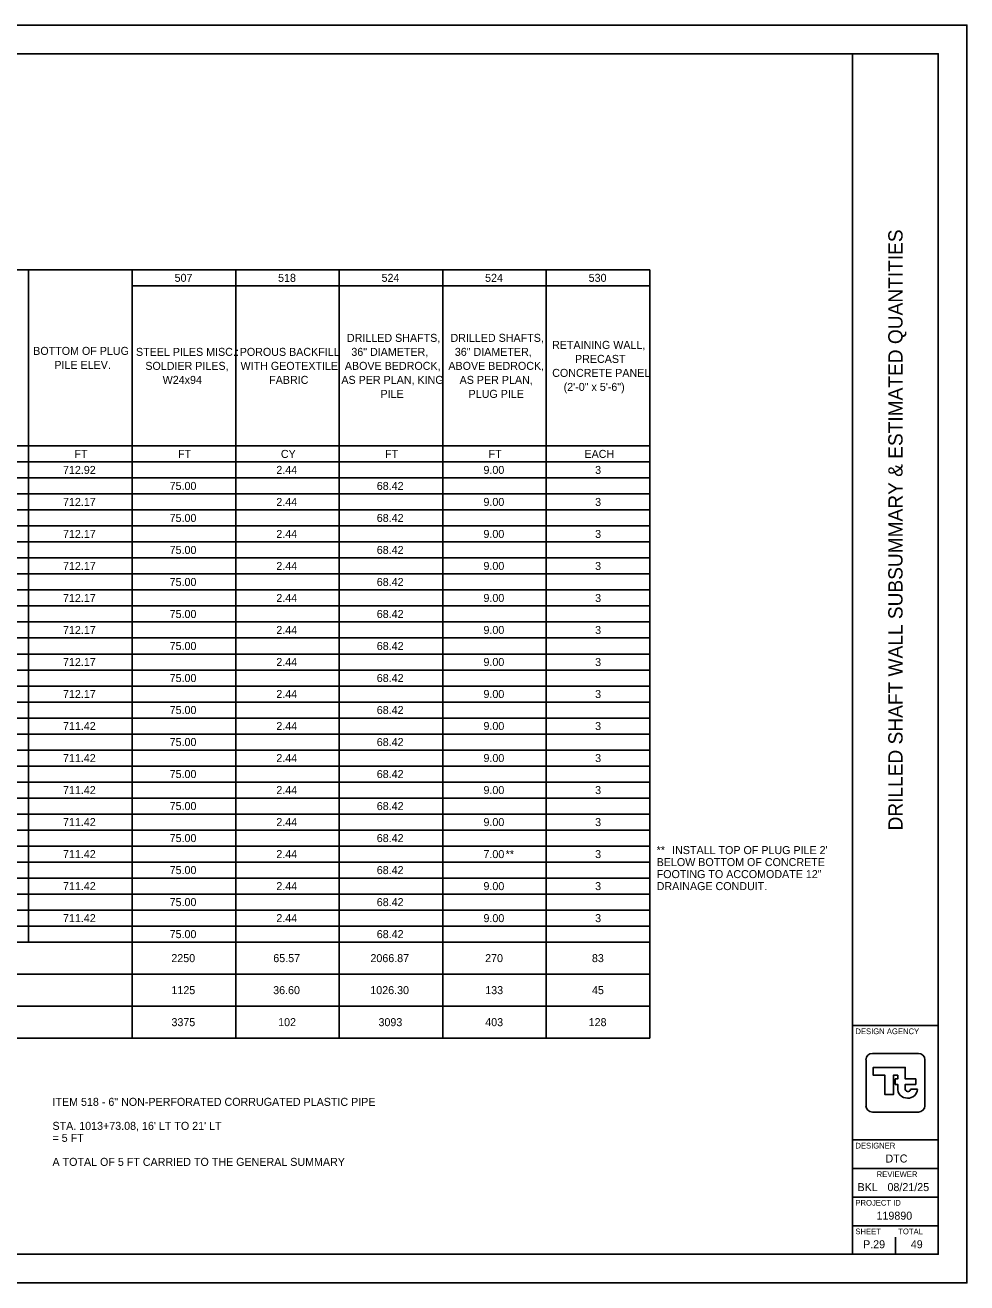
# Model space of a CAD drawing. Extents: x 0 to 34, y 0 to 22.
# Drawn here: x 17.52 to 34, y 0 to 22 of the extents above; entities that cross this region are included whole.
import ezdxf

# ---------------------------------------------------------------- set-up
doc = ezdxf.new("R2010")
doc.units = 0
for name, color, linetype in [('SH_Border', 7, 'Continuous'), ('SH_Cut_Line', 7, 'Continuous'), ('SH_Data', 7, 'Continuous'), ('SH_Text', 7, 'Continuous')]:
    doc.layers.add(name, color=color, linetype=linetype)

msp = doc.modelspace()

# ---------------------------------------------------------------- linework, layer by layer
at = {"layer": 'SH_Border'}
for p, q in [((32, 0.5), (32, 21.5)), ((32, 4.5), (33.5, 4.5)), ((32, 2.5), (33.5, 2.5)), ((32, 2), (33.5, 2)), ((32, 1.5), (33.5, 1.5)), ((32, 1), (33.5, 1))]:
    msp.add_line(p, q, dxfattribs=at)
msp.add_lwpolyline([(1.5, 21.5), (33.5, 21.5), (33.5, 0.5), (1.5, 0.5)], close=True, dxfattribs=at)
at = {"layer": 'SH_Cut_Line'}
msp.add_lwpolyline([(0, 0), (34, 0), (34, 22), (0, 22)], close=True, dxfattribs=at)
at = {"layer": 'SH_Data'}
for p, q in [((5.048, 17.72), (28.452, 17.72)), ((17.582, 17.72), (17.582, 5.96)), ((19.394, 17.72), (19.394, 4.28)), ((21.205, 17.72), (21.205, 4.28)), ((23.017, 17.72), (23.017, 4.28)), ((24.829, 17.72), (24.829, 4.28)), ((26.641, 17.72), (26.641, 4.28)), ((28.452, 17.72), (28.452, 4.28)), ((19.394, 17.44), (28.452, 17.44)), ((7.864, 14.64), (28.452, 14.64)), ((5.048, 14.36), (28.452, 14.36)), ((5.048, 14.08), (28.452, 14.08)), ((5.048, 13.8), (28.452, 13.8)), ((5.048, 13.52), (28.452, 13.52)), ((5.048, 13.24), (28.452, 13.24)), ((5.048, 12.96), (28.452, 12.96)), ((5.048, 12.68), (28.452, 12.68)), ((5.048, 12.4), (28.452, 12.4)), ((5.048, 12.12), (28.452, 12.12)), ((5.048, 11.84), (28.452, 11.84)), ((5.048, 11.56), (28.452, 11.56)), ((5.048, 11.28), (28.452, 11.28)), ((5.048, 11), (28.452, 11)), ((5.048, 10.72), (28.452, 10.72)), ((5.048, 10.44), (28.452, 10.44)), ((5.048, 10.16), (28.452, 10.16)), ((5.048, 9.88), (28.452, 9.88)), ((5.048, 9.6), (28.452, 9.6)), ((5.048, 9.32), (28.452, 9.32)), ((5.048, 9.04), (28.452, 9.04)), ((5.048, 8.76), (28.452, 8.76)), ((5.048, 8.48), (28.452, 8.48)), ((5.048, 8.2), (28.452, 8.2)), ((5.048, 7.92), (28.452, 7.92)), ((5.048, 7.64), (28.452, 7.64)), ((5.048, 7.36), (28.452, 7.36)), ((5.048, 7.08), (28.452, 7.08)), ((5.048, 6.8), (28.452, 6.8)), ((5.048, 6.52), (28.452, 6.52)), ((5.048, 6.24), (28.452, 6.24)), ((5.048, 5.96), (28.452, 5.96)), ((5.048, 5.4), (28.452, 5.4)), ((5.048, 4.84), (28.452, 4.84)), ((5.048, 4.28), (28.452, 4.28)), ((32.75, 3.5), (32.75, 3.5)), ((32.791, 3.415), (32.791, 3.415)), ((33.136, 3.385), (33.015, 3.385)), ((32.375, 0.675), (32.375, 0.675)), ((32.75, 0.5), (32.75, 0.8))]:
    msp.add_line(p, q, dxfattribs=at)
for points in [[(32.348, 4.014), (33.152, 4.014)], [(32.236, 3.099), (32.236, 3.901)], [(32.922, 3.399), (32.922, 3.47), (33.107, 3.47), (33.107, 3.568), (32.922, 3.568), (32.922, 3.768), (32.361, 3.768), (32.361, 3.632), (32.566, 3.632), (32.566, 3.294), (32.715, 3.294), (32.715, 3.63), (32.79, 3.63), (32.79, 3.568), (32.748, 3.568), (32.748, 3.47), (32.79, 3.47), (32.79, 3.415), (32.791, 3.415)], [(33.264, 3.901), (33.264, 3.099)], [(33.152, 2.986), (32.348, 2.986)]]:
    msp.add_lwpolyline(points, dxfattribs=at)
for centre, radius, start, end in [((32.348, 3.901), 0.113, 90, 180), ((33.152, 3.901), 0.113, 360, 90), ((32.949, 3.392), 0.16, 171.8856, 274.8323), ((32.968, 3.392), 0.0473, 171.8856, 350.9243), ((32.976, 3.392), 0.16, 265.1677, 357.3201), ((32.348, 3.099), 0.113, 180, 270), ((33.152, 3.099), 0.113, 270, 360)]:
    msp.add_arc(centre, radius, start, end, dxfattribs=at)

# ---------------------------------------------------------------- texts
msp.add_text('DRILLED SHAFT WALL SUBSUMMARY & ESTIMATED QUANTITIES', height=0.25, rotation=90, dxfattribs=at).set_placement((32.875, 7.913))
for s, height, p in [('DESIGN AGENCY', 0.1, (32.05, 4.35)), ('DESIGNER', 0.1, (32.05, 2.35)), ('DTC', 0.14, (32.576, 2.105)), ('REVIEWER', 0.1, (32.422, 1.85)), ('BKL', 0.14, (32.087, 1.605)), ('08/21/25', 0.14, (32.611, 1.605)), ('PROJECT ID', 0.1, (32.05, 1.35)), ('119890', 0.14, (32.419, 1.105)), ('SHEET', 0.1, (32.05, 0.85)), ('TOTAL', 0.1, (32.8, 0.85)), ('P.29', 0.14, (32.184, 0.605)), ('49', 0.14, (33.019, 0.605))]:
    msp.add_text(s, height=height, dxfattribs=at).set_placement(p)
at = {"layer": 'SH_Text'}
for s, p in [('507', (20.136, 17.51)), ('518', (21.947, 17.51)), ('524', (23.758, 17.51)), ('524', (25.569, 17.51)), ('530', (27.382, 17.51)), ('DRILLED SHAFTS, ', (23.152, 16.46)), ('DRILLED SHAFTS, ', (24.964, 16.46)), ('BOTTOM OF PLUG ', (17.662, 16.232)), ('STEEL PILES MISC.: ', (19.46, 16.215)), ('POROUS BACKFILL ', (21.276, 16.215)), ('36" DIAMETER, ', (23.229, 16.215)), ('36" DIAMETER, ', (25.04, 16.215)), ('RETAINING WALL, ', (26.741, 16.337)), ('PILE ELEV.', (18.032, 15.987)), ('SOLDIER PILES, ', (19.624, 15.97)), ('WITH GEOTEXTILE ', (21.29, 15.97)), ('ABOVE BEDROCK, ', (23.115, 15.97)), ('ABOVE BEDROCK, ', (24.927, 15.97)), ('PRECAST ', (27.143, 16.092)), ('W24x94', (19.927, 15.725)), ('FABRIC', (21.791, 15.725)), ('AS PER PLAN, KING ', (23.055, 15.725)), ('AS PER PLAN, ', (25.124, 15.725)), ('CONCRETE PANEL ', (26.744, 15.847)), ('PLUG PILE', (25.281, 15.48)), ('(2\'-0" x 5\'-6")', (26.944, 15.602)), ('PILE', (23.739, 15.48)), ('FT', (18.383, 14.43)), ('FT', (20.195, 14.43)), ('CY', (21.996, 14.43)), ('FT', (23.818, 14.43)), ('FT', (25.63, 14.43)), ('EACH', (27.308, 14.43)), ('712.92', (18.183, 14.15)), ('2.44', (21.916, 14.15)), ('9.00', (25.541, 14.15)), ('3', (27.495, 14.15)), ('75.00', (20.049, 13.87)), ('68.42', (23.674, 13.87)), ('712.17', (18.183, 13.59)), ('2.44', (21.916, 13.59)), ('9.00', (25.541, 13.59)), ('3', (27.495, 13.59)), ('75.00', (20.049, 13.31)), ('68.42', (23.674, 13.31)), ('712.17', (18.183, 13.03)), ('2.44', (21.916, 13.03)), ('9.00', (25.541, 13.03)), ('3', (27.495, 13.03)), ('75.00', (20.049, 12.75)), ('68.42', (23.674, 12.75)), ('712.17', (18.183, 12.47)), ('2.44', (21.916, 12.47)), ('9.00', (25.541, 12.47)), ('3', (27.495, 12.47)), ('75.00', (20.049, 12.19)), ('68.42', (23.674, 12.19)), ('712.17', (18.183, 11.91)), ('2.44', (21.916, 11.91)), ('9.00', (25.541, 11.91)), ('3', (27.495, 11.91)), ('75.00', (20.049, 11.63)), ('68.42', (23.674, 11.63)), ('712.17', (18.183, 11.35)), ('2.44', (21.916, 11.35)), ('9.00', (25.541, 11.35)), ('3', (27.495, 11.35)), ('75.00', (20.049, 11.07)), ('68.42', (23.674, 11.07)), ('712.17', (18.183, 10.79)), ('2.44', (21.916, 10.79)), ('9.00', (25.541, 10.79)), ('3', (27.495, 10.79)), ('75.00', (20.049, 10.51)), ('68.42', (23.674, 10.51)), ('712.17', (18.183, 10.23)), ('2.44', (21.916, 10.23)), ('9.00', (25.541, 10.23)), ('3', (27.495, 10.23)), ('75.00', (20.049, 9.95)), ('68.42', (23.674, 9.95)), ('711.42', (18.183, 9.67)), ('2.44', (21.916, 9.67)), ('9.00', (25.541, 9.67)), ('3', (27.495, 9.67)), ('75.00', (20.049, 9.39)), ('68.42', (23.674, 9.39)), ('711.42', (18.183, 9.11)), ('2.44', (21.916, 9.11)), ('9.00', (25.541, 9.11)), ('3', (27.495, 9.11)), ('75.00', (20.049, 8.83)), ('68.42', (23.674, 8.83)), ('711.42', (18.183, 8.55)), ('2.44', (21.916, 8.55)), ('9.00', (25.541, 8.55)), ('3', (27.495, 8.55)), ('75.00', (20.049, 8.27)), ('68.42', (23.674, 8.27)), ('711.42', (18.183, 7.99)), ('2.44', (21.916, 7.99)), ('9.00', (25.541, 7.99)), ('3', (27.495, 7.99)), ('75.00', (20.049, 7.71)), ('68.42', (23.674, 7.71)), ('711.42', (18.183, 7.43)), ('2.44', (21.916, 7.43)), ('7.00', (25.541, 7.43)), ('**', (25.929, 7.43)), ('3', (27.495, 7.43)), ('**', (28.572, 7.5)), (" INSTALL TOP OF PLUG PILE 2' ", (28.791, 7.5)), ('75.00', (20.049, 7.15)), ('68.42', (23.674, 7.15)), ('BELOW BOTTOM OF CONCRETE ', (28.572, 7.29)), ('FOOTING TO ACCOMODATE 12" ', (28.572, 7.08)), ('711.42', (18.183, 6.87)), ('2.44', (21.916, 6.87)), ('9.00', (25.541, 6.87)), ('3', (27.495, 6.87)), ('DRAINAGE CONDUIT.', (28.572, 6.87)), ('75.00', (20.049, 6.59)), ('68.42', (23.674, 6.59)), ('711.42', (18.183, 6.31)), ('2.44', (21.916, 6.31)), ('9.00', (25.541, 6.31)), ('3', (27.495, 6.31)), ('75.00', (20.049, 6.03)), ('68.42', (23.674, 6.03)), ('2250', (20.079, 5.61)), ('65.57', (21.863, 5.61)), ('2066.87', (23.563, 5.61)), ('270', (25.57, 5.61)), ('83', (27.439, 5.61)), ('1125', (20.081, 5.05)), ('36.60', (21.861, 5.05)), ('1026.30', (23.561, 5.05)), ('133', (25.572, 5.05)), ('45', (27.44, 5.05)), ('3375', (20.081, 4.49)), ('102', (21.948, 4.49)), ('3093', (23.704, 4.49)), ('403', (25.572, 4.49)), ('128', (27.382, 4.49)), ('ITEM 518 - 6" NON-PERFORATED CORRUGATED PLASTIC PIPE', (17.999, 3.096)), ("STA. 1013+73.08, 16' LT TO 21' LT ", (17.999, 2.676)), ('= 5 FT', (17.999, 2.466)), ('A TOTAL OF 5 FT CARRIED TO THE GENERAL SUMMARY', (17.999, 2.046))]:
    msp.add_text(s, height=0.14, dxfattribs=at).set_placement(p)

doc.saveas('drawing.dxf')
